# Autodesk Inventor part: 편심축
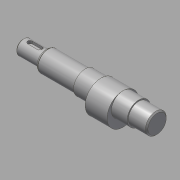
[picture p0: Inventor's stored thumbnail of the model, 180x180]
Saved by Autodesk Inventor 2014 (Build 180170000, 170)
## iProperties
Created: 2017-08
Part Number: 편심축
Material: 강철, 연강
Document SubType Name: Modeling
Designer: mduedu
Density: 1 g/cm^3
Appearance: 강철
Author: mduedu
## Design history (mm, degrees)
sketch "스케치1"
  geometry: L1 (0, 0)-(110, 0); L2 (110, 0)-(110, 8.5); L3 (110, 8.5)-(95, 8.5); L4 (95, 8.5)-(95, 9.5); L5 (95, 9.5)-(51, 9.5); L6 (51, 9.5)-(51, 8.5); L7 (51, 8.5)-(19, 8.5); L8 (19, 8.5)-(19, 6); L9 (19, 6)-(0, 6); L10 (0, 6)-(0, 0)
  constraints: 20 end point, 6 parallel, 2 collinear, 2 perpendicular, 1 horizontal
  dimensions: "d0" = 110 distance of L1.start L1.end; "d1" = 17 diameter of L3 L1; "d2" = 19 diameter of L5 L1; "d3" = 12 diameter of L9 L1; "d4" = 19 distance of L8.end L9.end; "d5" = 15 distance of L2.end L3.end; "d6" = 44 distance of L4.end L5.end
revolve "회전1" sketch "스케치1" stored, may be unused: angle "d7" = 90 deg
node "작업 평면1"
sketch "스케치2"
  geometry: C1 r 9.5 at (0, 0) reference; C2 r 13 at (0, -3.5); 1 further point
  constraints: 1 centre point, 1 tangent, 1 vertical alignment
  dimensions: "d8" = 3.5 distance of point (0, 0) C2.centre
extrude "돌출1" join sketch "스케치2" stored distance "d9" = 18; taper "d10" = 0 deg
chamfer "모따기1" distance "d11" = 1; stored, may be unused: second distance "d12" = 2, angle "d13" = 45 deg
node "작업 평면2"
sketch "스케치3"
  geometry: L1 (3.5, -2)-(-4.5, -2); L2 (-4.5, -2)-(-4.5, 2); L3 (-4.5, 2)-(3.5, 2); L4 (3.5, 2)-(3.5, -2); L5 (9.5, 6)-(9.5, -6) reference; A1 r 2 centre (3.5, 0) between (3.5, -2) and (3.5, 2); A2 r 2 centre (-4.5, 0) between (-4.5, 2) and (-4.5, -2); A3 r 2 centre (3.5, 0) between (3.5, 2) and (3.5, -2); A4 r 2 centre (-4.5, 0) between (-4.5, -2) and (-4.5, 2); 1 further point
  constraints: 8 end point, 8 point on circle, 4 centre point, 2 midpoint, 2 parallel, 1 horizontal, 1 horizontal alignment, 1 perpendicular
  dimensions: "d14" = 12 dimension on A2 A1; "d16" = 4 distance between parallel lines of L3 L1; "d17" = 4 distance edge to line of A1 L5
extrude "돌출2" cut sketch "스케치3" distance "d18" = 2.5; taper "d19" = 0 deg
chamfer "모따기2" distance "d20" = 1; stored, may be unused: second distance "d21" = 2, angle "d22" = 45 deg
chamfer "모따기3" distance "d23" = 1; stored, may be unused: second distance "d24" = 2, angle "d25" = 60 deg
fillet "모깎기1" dims "d26" = 0.5
hole "구멍1" diameter "d29" = 3.242; stored, may be unused: countersink angle "d33" = 90 deg, drill point angle "d35" = 118 deg; dims "d30" = 8, "d31" = 4, "d32" = 2, "d34" = 10, "d36" = 10, "d37" = 10
node "솔리드1"
node "절단 모서리 투영1"
